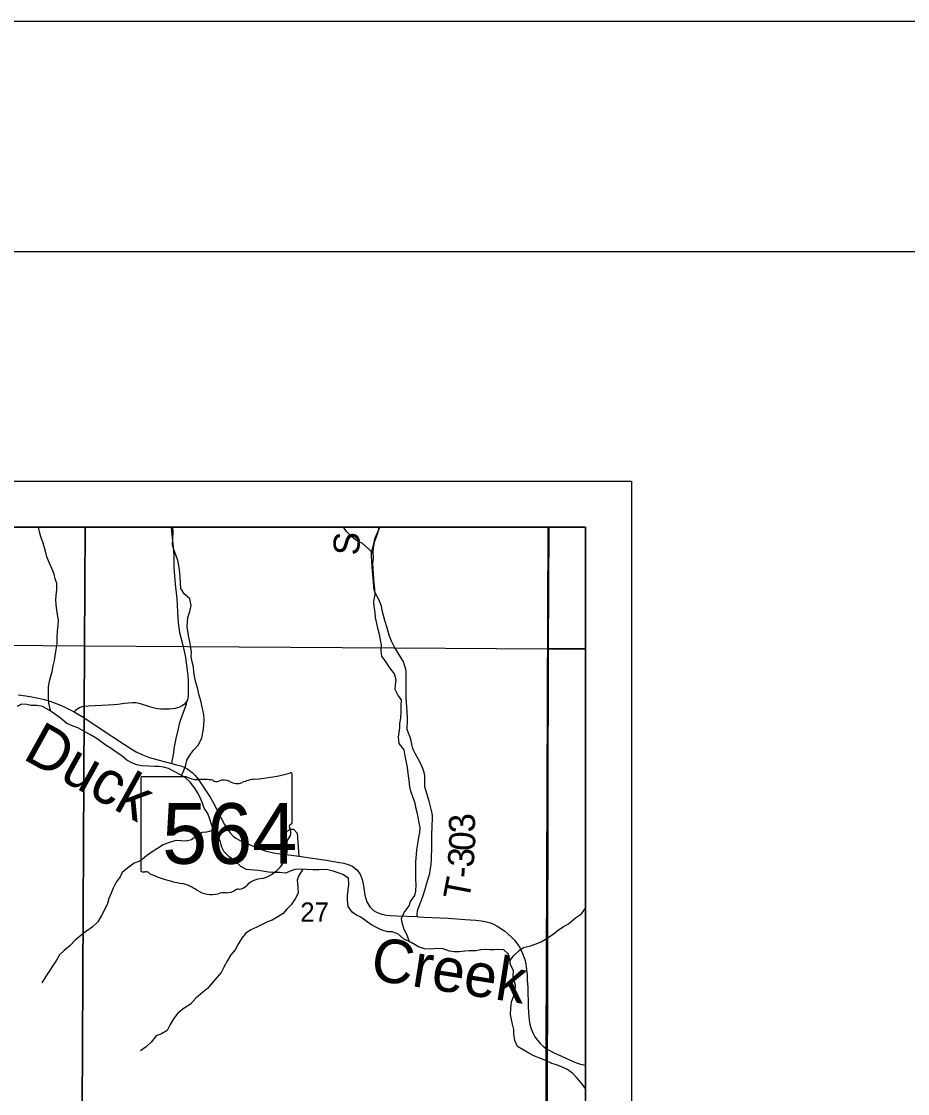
# Model space of a CAD drawing. Extents: x 0 to 34, y 0 to 22.
# Drawn here: x 7.673 to 9.601, y 19.668 to 22 of the extents above; entities that cross this region are included whole.
import ezdxf

# ---------------------------------------------------------------- set-up
doc = ezdxf.new("R2010")
doc.units = 0
for name, color, linetype in [('Default', 7, 'Continuous'), ('GM_X_Minor_River', 7, 'Continuous'), ('GM_X_Minor_River_Text', 7, 'Continuous'), ('GM_X_Rail_Line', 7, 'Continuous'), ('GM_X_Section', 7, 'Continuous'), ('GM_X_Section_Text', 7, 'Continuous'), ('GM_X_State_Location', 7, 'Continuous'), ('GM_X_State_Route', 7, 'Continuous'), ('GM_X_State_Shield', 7, 'Continuous'), ('GM_X_Township_Road', 7, 'Continuous'), ('GM_X_Township_Road_Text', 7, 'Continuous'), ('SH_Border', 7, 'Continuous'), ('SH_Cut_Line', 7, 'Continuous'), ('SH_Data', 7, 'Continuous')]:
    doc.layers.add(name, color=color, linetype=linetype)

msp = doc.modelspace()

# ---------------------------------------------------------------- linework, layer by layer
at = {"layer": 'Default'}
for points in [[(7.8121, 20.9), (6.8087, 20.9), (6.806, 20.65), (7.8107, 20.6421)], [(8.8202, 20.9), (7.8121, 20.9), (7.8107, 20.6421), (8.8188, 20.6358)], [(8.9, 20.6353), (8.9, 20.9), (8.8202, 20.9), (8.8188, 20.6358)], [(8.9, 19.6293), (8.9, 20.6353), (8.8188, 20.6358), (8.8166, 19.6292)]]:
    msp.add_lwpolyline(points, close=True, dxfattribs=at)
at = {"layer": 'GM_X_Minor_River'}
for points in [[(7.7374, 20.4995), (7.733, 20.5171), (7.7326, 20.5307), (7.7325, 20.5527), (7.7343, 20.5649), (7.7377, 20.5759), (7.7403, 20.5865), (7.7425, 20.5983), (7.7455, 20.6101), (7.747, 20.62), (7.7492, 20.634), (7.751, 20.6473), (7.751, 20.661), (7.7517, 20.6739), (7.7532, 20.6876), (7.7542, 20.697), (7.7504, 20.7198), (7.7488, 20.7323), (7.7484, 20.7418), (7.7487, 20.7513), (7.7502, 20.7638), (7.7501, 20.7775), (7.747, 20.7881), (7.7443, 20.7983), (7.7405, 20.8089), (7.7336, 20.823), (7.729, 20.8355), (7.7255, 20.8483), (7.7228, 20.8578), (7.7201, 20.8677), (7.7158, 20.879), (7.7124, 20.8897), (7.7104, 20.8999), (7.7104, 20.9)], [(8.0213, 20.3604), (8.0265, 20.3707), (8.031, 20.3836), (8.0328, 20.3931), (8.0392, 20.4026), (8.0471, 20.4144), (8.0585, 20.427), (8.066, 20.4419), (8.0686, 20.457), (8.0701, 20.4681), (8.0712, 20.4817), (8.0703, 20.492), (8.0657, 20.5124), (8.0634, 20.5223), (8.0595, 20.5371), (8.0572, 20.5481), (8.0529, 20.5625), (8.0499, 20.5758), (8.0487, 20.5856), (8.0475, 20.5966), (8.0448, 20.6076), (8.0428, 20.6179), (8.0432, 20.6281), (8.0416, 20.6387), (8.0396, 20.6516), (8.0373, 20.6611), (8.035, 20.6736), (8.0338, 20.6835), (8.0345, 20.6945), (8.0356, 20.704), (8.0394, 20.7165), (8.0423, 20.7298), (8.0396, 20.7442), (8.0282, 20.7548), (8.0201, 20.7669), (8.0193, 20.7775), (8.0185, 20.7927), (8.0169, 20.8075), (8.0154, 20.817), (8.0134, 20.8276), (8.0103, 20.8378), (8.0046, 20.8515), (8.0023, 20.8617), (8.0026, 20.875), (8.0033, 20.889), (8.0029, 20.9)], [(8.4388, 20.8421), (8.4276, 20.8537), (8.415, 20.8643), (8.4002, 20.8726), (8.3903, 20.8805), (8.3807, 20.8911), (8.3736, 20.9)], [(8.5173, 19.9986), (8.5118, 20.0142), (8.5057, 20.0255), (8.5011, 20.0399), (8.5003, 20.0494), (8.5059, 20.0623), (8.5165, 20.0764), (8.5199, 20.0863), (8.5293, 20.0989), (8.5315, 20.1088), (8.5319, 20.1228), (8.5311, 20.1334), (8.531, 20.1558), (8.5313, 20.1725), (8.5323, 20.1881), (8.5334, 20.1987), (8.5356, 20.2116), (8.5379, 20.2253), (8.5401, 20.2359), (8.5404, 20.2469), (8.5385, 20.2572), (8.5362, 20.2693), (8.5338, 20.2796), (8.5315, 20.2902), (8.5299, 20.3), (8.5253, 20.3118), (8.52, 20.3258), (8.5184, 20.3357), (8.5164, 20.3489), (8.5152, 20.3592), (8.514, 20.3717), (8.5125, 20.3816), (8.5098, 20.3922), (8.5078, 20.4028), (8.5059, 20.4157), (8.4952, 20.4297), (8.4936, 20.4433), (8.4951, 20.4536), (8.4962, 20.4635), (8.4965, 20.473), (8.4984, 20.4847), (8.4991, 20.4992), (8.4994, 20.5124), (8.5001, 20.5246), (8.4928, 20.5344), (8.4859, 20.5469), (8.487, 20.5576), (8.4885, 20.5671), (8.4846, 20.5811), (8.4747, 20.5939), (8.4667, 20.6068), (8.4575, 20.6197), (8.4559, 20.6311), (8.4563, 20.6443), (8.4543, 20.6546), (8.4528, 20.6641), (8.4493, 20.6773), (8.4462, 20.691), (8.4438, 20.7039), (8.4427, 20.7156), (8.4403, 20.7278), (8.4399, 20.7384), (8.4425, 20.754), (8.442, 20.7669), (8.4405, 20.7779), (8.4401, 20.7874), (8.4393, 20.7991), (8.4381, 20.8094), (8.438, 20.8219), (8.4391, 20.8325), (8.4387, 20.845), (8.4394, 20.8549), (8.442, 20.8694), (8.4454, 20.8792), (8.4491, 20.8891), (8.4516, 20.9)], [(8.3823, 20.0982), (8.3838, 20.1112), (8.3857, 20.1241), (8.3848, 20.137), (8.3723, 20.1449), (8.3624, 20.1482), (8.3517, 20.152), (8.3399, 20.1546), (8.3301, 20.1557), (8.3206, 20.1553), (8.3077, 20.1552), (8.2936, 20.1555), (8.2811, 20.1566), (8.2682, 20.1558), (8.2579, 20.1524), (8.2481, 20.1478), (8.2344, 20.1488), (8.2203, 20.1495), (8.2105, 20.1502), (8.1979, 20.1521), (8.1884, 20.1536), (8.1626, 20.1557), (8.1504, 20.1621), (8.1382, 20.1735), (8.1253, 20.1833), (8.1142, 20.1939), (8.1092, 20.2045), (8.1054, 20.2173), (8.1023, 20.2268), (8.0935, 20.2397), (8.0881, 20.2495), (8.0831, 20.2651), (8.0785, 20.2776), (8.0712, 20.2893), (8.067, 20.2999), (8.062, 20.3124), (8.0563, 20.323), (8.0505, 20.3329), (8.0406, 20.3457), (8.0292, 20.3559), (8.0178, 20.3623), (8.0067, 20.3683), (7.993, 20.3751), (7.9827, 20.3785), (7.9729, 20.3796), (7.9634, 20.3799), (7.9505, 20.3806), (7.9356, 20.3813), (7.9246, 20.3835), (7.9147, 20.3869), (7.9026, 20.3933), (7.8919, 20.4028), (7.8793, 20.4107), (7.8683, 20.4186), (7.858, 20.4254), (7.8458, 20.4344), (7.8363, 20.4416), (7.8222, 20.4495), (7.8089, 20.4563), (7.7959, 20.4638), (7.786, 20.4676), (7.7719, 20.4732), (7.7586, 20.4849), (7.7457, 20.4943), (7.7335, 20.5019), (7.7194, 20.5102), (7.7076, 20.5124), (7.6947, 20.5127), (7.6852, 20.5142), (7.6738, 20.5153), (7.6639, 20.5103)], [(8.0928, 20.241), (8.076, 20.237), (8.0665, 20.2362), (8.0559, 20.2293), (8.0434, 20.2201), (8.0317, 20.217), (8.0211, 20.2177), (8.01, 20.2188), (7.9971, 20.215), (7.9816, 20.2092), (7.9695, 20.2012), (7.9596, 20.1955), (7.9456, 20.1852), (7.9324, 20.1745), (7.9184, 20.1695), (7.9044, 20.1588), (7.8922, 20.1492), (7.8881, 20.1397), (7.8798, 20.1279), (7.8726, 20.1154), (7.8685, 20.104), (7.8633, 20.0926), (7.8603, 20.0816), (7.8554, 20.0709), (7.8478, 20.0553), (7.8399, 20.042), (7.8271, 20.0302), (7.815, 20.0218), (7.8028, 20.0122), (7.79, 20.0019), (7.7786, 19.9898), (7.7665, 19.9798), (7.7563, 19.9703), (7.7495, 19.9585), (7.7412, 19.9456), (7.7348, 19.9353), (7.7258, 19.922), (7.7179, 19.909)], [(8.2852, 20.1563), (8.277, 20.1429), (8.2732, 20.1327), (8.2748, 20.1171), (8.2752, 20.1042), (8.2685, 20.0917), (8.2598, 20.0791), (8.2507, 20.0696), (8.2424, 20.0601), (8.2307, 20.0524), (8.2185, 20.0455), (8.2087, 20.0417), (8.1969, 20.0363), (8.1852, 20.0302), (8.1727, 20.0245), (8.1606, 20.0164), (8.1526, 20.0065), (8.1458, 19.9944), (8.1383, 19.9811), (8.1289, 19.97), (8.1217, 19.9575), (8.1138, 19.943), (8.1078, 19.932), (8.0942, 19.916), (8.0859, 19.9065), (8.0779, 19.8969), (8.0669, 19.8885), (8.0537, 19.8763), (8.0412, 19.8626), (8.0276, 19.8538), (8.0136, 19.8432), (8.0042, 19.8306), (7.997, 19.8184), (7.9906, 19.8059), (7.9777, 19.7982), (7.9663, 19.794), (7.9554, 19.7803), (7.9448, 19.77), (7.9323, 19.7612)], [(8.9, 19.6793), (8.8907, 19.6917), (8.8823, 19.7016), (8.8717, 19.7129), (8.8595, 19.7212), (8.8465, 19.7272), (8.837, 19.731), (8.8271, 19.734), (8.8119, 19.7407), (8.7986, 19.7464), (8.7879, 19.7501), (8.7769, 19.7561), (8.7647, 19.7633), (8.7522, 19.7705), (8.7468, 19.7837), (8.7444, 19.7981), (8.744, 19.8076), (8.7417, 19.8194), (8.7394, 19.8296), (8.7374, 19.8406), (8.7381, 19.8531), (8.7396, 19.8679), (8.7441, 19.8812), (8.7474, 19.8922), (8.7482, 19.904), (8.7454, 19.9142), (8.7431, 19.9237), (8.7435, 19.9355), (8.7373, 19.9491), (8.7358, 19.9594), (8.7327, 19.9715), (8.7224, 19.9809), (8.7114, 19.9816), (8.7019, 19.9808), (8.6916, 19.9812), (8.6817, 19.9815), (8.6722, 19.9807), (8.6616, 19.9791), (8.6472, 19.9787), (8.6377, 19.9783), (8.6263, 19.9767), (8.6145, 19.9763), (8.6047, 19.9781), (8.5906, 19.983), (8.5765, 19.9837), (8.564, 19.9825), (8.5499, 19.9828), (8.537, 19.9877), (8.5222, 19.9964), (8.5043, 20.0047), (8.4917, 20.016), (8.4799, 20.0201), (8.4704, 20.0204), (8.4575, 20.0238), (8.4457, 20.0294), (8.4331, 20.0358), (8.4228, 20.0438), (8.4114, 20.0517), (8.4019, 20.0566), (8.3924, 20.063), (8.384, 20.0751), (8.3824, 20.0888), (8.3823, 20.0982)], [(8.736, 19.9576), (8.7426, 19.9674), (8.7558, 19.9792), (8.7656, 19.9857), (8.7808, 19.9895), (8.791, 19.993), (8.8039, 19.9987), (8.8153, 20.0056), (8.8301, 20.0152), (8.8418, 20.0247), (8.8516, 20.0308), (8.863, 20.0373), (8.8785, 20.0507), (8.8914, 20.0591), (8.9, 20.0714)]]:
    msp.add_lwpolyline(points, dxfattribs=at)
at = {"layer": 'GM_X_Rail_Line'}
for points in [[(5.4171, 18.6266), (7.3845, 18.6186), (7.3876, 18.6186), (7.7217, 18.6188), (7.7247, 18.6188), (7.7665, 18.6188), (7.7949, 18.6196), (7.7955, 18.662), (7.7955, 18.6643), (7.8036, 19.6113), (7.8037, 19.6169), (7.8038, 19.6317), (8.8143, 19.6303), (8.8149, 19.7665), (8.8193, 20.9), (4.5874, 20.9)], [(8.9, 14.624), (8.9, 20.9), (8.8193, 20.9), (8.8149, 19.7665), (8.8143, 19.6303), (7.8038, 19.6317), (7.8037, 19.6169), (7.8036, 19.6113), (7.7955, 18.6643), (7.7955, 18.662), (7.7949, 18.6196), (7.7665, 18.6188), (7.7247, 18.6188), (7.7217, 18.6188), (7.3876, 18.6186), (7.3845, 18.6186), (5.4171, 18.6266)]]:
    msp.add_lwpolyline(points, dxfattribs=at)
at = {"layer": 'GM_X_Section'}
for points in [[(6.806, 20.65), (7.8107, 20.6421), (7.8055, 19.6329), (6.8002, 19.6351)], [(7.8107, 20.6421), (8.8188, 20.6358), (8.8166, 19.6292), (7.8055, 19.6329)]]:
    msp.add_lwpolyline(points, close=True, dxfattribs=at)
at = {"layer": 'GM_X_State_Route'}
for points in [[(7.666, 20.5356), (7.6827, 20.5331), (7.6963, 20.5311), (7.7107, 20.5284), (7.7235, 20.5252), (7.7396, 20.5205), (7.7622, 20.5118), (7.7882, 20.4983), (7.8088, 20.4859), (7.8449, 20.4623), (7.8978, 20.4272), (7.9123, 20.4179), (7.9232, 20.4115), (7.9356, 20.4055), (7.9498, 20.4), (7.962, 20.3964), (7.9806, 20.391), (8.0006, 20.3862), (8.008, 20.3841), (8.0134, 20.3827), (8.0199, 20.3809), (8.027, 20.3782), (8.0334, 20.3751), (8.0392, 20.3713), (8.0447, 20.3666), (8.0503, 20.361), (8.0554, 20.3548), (8.0651, 20.3413), (8.0695, 20.3346), (8.0766, 20.3241), (8.0836, 20.313), (8.0901, 20.3016), (8.0952, 20.2921), (8.0992, 20.2842), (8.1069, 20.2687), (8.115, 20.2533), (8.1207, 20.244), (8.1274, 20.2355), (8.134, 20.2281), (8.1396, 20.2238), (8.1449, 20.2206), (8.1515, 20.2173), (8.1646, 20.2119)], [(8.1646, 20.2119), (8.1805, 20.2053), (8.1936, 20.1999), (8.2036, 20.1965), (8.2219, 20.1921), (8.2408, 20.1892), (8.261, 20.1865), (8.2768, 20.1846), (8.3359, 20.176), (8.3654, 20.1711), (8.3747, 20.1693), (8.3843, 20.1664), (8.3933, 20.1627), (8.4032, 20.1553), (8.4102, 20.1455), (8.4146, 20.1341), (8.4167, 20.1248), (8.4184, 20.1151), (8.4206, 20.1001), (8.4247, 20.0857), (8.4314, 20.0743), (8.4394, 20.0667), (8.4469, 20.0618), (8.4572, 20.0584), (8.4677, 20.0562), (8.4762, 20.0554), (8.4902, 20.0549), (8.5339, 20.0532), (8.5377, 20.0529), (8.5491, 20.0523), (8.5842, 20.0505)], [(8.5842, 20.0505), (8.6013, 20.0496), (8.6382, 20.0473), (8.6617, 20.0458), (8.674, 20.0439), (8.6849, 20.042), (8.6934, 20.0394), (8.7016, 20.036), (8.7084, 20.0323), (8.7139, 20.029), (8.7241, 20.022), (8.7322, 20.0153), (8.7395, 20.0086), (8.7462, 20.0011), (8.7524, 19.9933), (8.7573, 19.9857), (8.7631, 19.9732), (8.768, 19.9597), (8.7706, 19.9496), (8.7712, 19.944), (8.7731, 19.926), (8.7735, 19.915), (8.7744, 19.8991), (8.7755, 19.8567), (8.7761, 19.8444), (8.7778, 19.8283), (8.7793, 19.8196), (8.782, 19.8089), (8.7861, 19.7991), (8.7899, 19.7921), (8.7947, 19.7849), (8.8022, 19.7766), (8.8089, 19.7711), (8.8151, 19.766), (8.832, 19.7573), (8.8482, 19.7495), (8.8785, 19.736), (8.8891, 19.7325), (8.9, 19.7299)]]:
    msp.add_lwpolyline(points, dxfattribs=at)
at = {"layer": 'GM_X_State_Shield'}
for p, q in [((8.0325, 20.3575), (7.936, 20.3575)), ((8.2624, 20.2578), (8.2624, 20.3625)), ((7.9328, 20.3541), (7.9328, 20.154)), ((8.2623, 20.2578), (8.2624, 20.2578))]:
    msp.add_line(p, q, dxfattribs=at)
for centre, major_axis, start_param, end_param in [((7.9366, 20.3545), (0.00382, 0), 1.712693, 3.28349), ((8.0555, 20.3807), (0.037, 0), 4.042523, 4.731795), ((8.145, 20.6303), (0.3495, 0), 4.814394, 5.042369), ((8.2587, 20.3629), (0.00367, 0), 6.141152, 7.989035), ((8.0678, 20.2452), (0.133, 0), 1.404758, 1.657858), ((8.098, 20.3555), (0.0107, 0), 3.836095, 5.185415), ((8.1137, 20.3324), (0.0222, 0), 0.950623, 2.079405), ((8.1423, 20.3641), (0.0267, 0), 4.081561, 5.145723), ((8.1895, 20.2964), (0.0703, 0), 1.699011, 2.107814), ((8.2615, 20.2501), (0.00568, 0), 1.883978, 3.671073), ((8.2254, 20.2369), (0.0341, 0), 5.934695, 6.695948), ((8.2584, 20.2574), (0.00393, 0), 5.05454, 6.418171), ((8.2755, 20.214), (0.0248, 0), 2.387724, 3.262537), ((8.1645, 20.2007), (0.0874, 0), 5.101752, 6.440018), ((7.9366, 20.1535), (0.00385, 0), 3.00124, 4.508301), ((7.9372, 20.174), (0.0294, 0), 4.665946, 4.897461), ((7.9432, 20.1424), (0.0106, 0), 0.519207, 1.627899), ((8.077, 20.3222), (0.2524, 0), 4.195997, 4.488961), ((8.0018, 20.064), (0.079, 0), 0.823519, 1.323587), ((8.2014, 20.0978), (0.0479, 0), 1.647645, 2.488434), ((8.0872, 20.1414), (0.0501, 0), 4.026481, 4.996735), ((8.1161, 20.0722), (0.0412, 0), 1.495662, 1.94098), ((8.1198, 20.1264), (0.0267, 0), 4.691044, 5.507374), ((8.1439, 20.107), (0.00752, 0), 1.147584, 2.315152), ((8.1407, 20.1346), (0.0282, 0), 4.937069, 5.64225)]:
    msp.add_ellipse(centre, major_axis=major_axis, ratio=0.8, start_param=start_param, end_param=end_param, dxfattribs=at)
at = {"layer": 'GM_X_Township_Road'}
for points in [[(7.9988, 20.9), (7.9998, 20.8918), (8.0033, 20.8569), (8.0046, 20.8375), (8.0051, 20.8121), (8.0081, 20.7763), (8.0112, 20.7444), (8.012, 20.7314), (8.0129, 20.7154), (8.0144, 20.6926), (8.0156, 20.6812), (8.0175, 20.6714), (8.0203, 20.6604), (8.0253, 20.6408), (8.03, 20.6169), (8.0335, 20.5945), (8.035, 20.5779), (8.036, 20.566), (8.0363, 20.5551), (8.0364, 20.5428), (8.0358, 20.5348), (8.0351, 20.5285), (8.0345, 20.5249), (8.0309, 20.5187), (8.0279, 20.5153), (8.0233, 20.5118), (8.019, 20.5094), (8.0152, 20.5079), (8.0068, 20.506), (7.9953, 20.5045), (7.9851, 20.5044), (7.9764, 20.5045), (7.9694, 20.5053), (7.9601, 20.507), (7.9504, 20.5099), (7.9323, 20.5163), (7.9225, 20.5181), (7.9149, 20.5183), (7.9054, 20.5177), (7.8977, 20.5165), (7.8828, 20.5146), (7.8737, 20.5136), (7.8621, 20.5128), (7.8337, 20.5115), (7.8189, 20.5112), (7.8096, 20.5104), (7.8046, 20.5094), (7.8, 20.5075), (7.7939, 20.5039), (7.7908, 20.5012), (7.7882, 20.4983)], [(8.5667, 20.2783), (8.5646, 20.2872), (8.5602, 20.3041), (8.5528, 20.3279), (8.5511, 20.3357), (8.551, 20.3545), (8.5506, 20.3599), (8.5494, 20.3666), (8.5461, 20.3756), (8.5396, 20.3896), (8.5296, 20.408), (8.5267, 20.4134), (8.5248, 20.4188), (8.5233, 20.4245), (8.5208, 20.4355), (8.5185, 20.4435), (8.5149, 20.4525), (8.5126, 20.4603), (8.5124, 20.4666), (8.5132, 20.4757), (8.5131, 20.4872), (8.5116, 20.5089), (8.5105, 20.5295), (8.5099, 20.545), (8.51, 20.5632), (8.5105, 20.5714), (8.5104, 20.5813), (8.5103, 20.586), (8.5094, 20.5916), (8.5068, 20.6004), (8.504, 20.607), (8.4998, 20.6142), (8.494, 20.6237), (8.4838, 20.641), (8.478, 20.6519), (8.4735, 20.6656), (8.4686, 20.6814), (8.4634, 20.6974), (8.458, 20.7191), (8.4562, 20.7286), (8.4539, 20.7359), (8.451, 20.7425), (8.447, 20.7497), (8.4428, 20.7575), (8.4408, 20.7636), (8.4398, 20.7704), (8.4391, 20.7807), (8.4381, 20.7892), (8.4363, 20.8129), (8.4356, 20.826), (8.4349, 20.8374), (8.4349, 20.844), (8.4356, 20.849), (8.4374, 20.8555), (8.4429, 20.8767), (8.4511, 20.8966), (8.4532, 20.9)], [(8.0006, 20.3862), (8.0042, 20.4059), (8.0064, 20.4222), (8.0101, 20.4404), (8.014, 20.4588), (8.0182, 20.4751), (8.0237, 20.4921), (8.0297, 20.5071), (8.0323, 20.5158), (8.0345, 20.5249)], [(8.5339, 20.0532), (8.5341, 20.0586), (8.5351, 20.0657), (8.5367, 20.0724), (8.5403, 20.0817), (8.5471, 20.0994), (8.5513, 20.1129), (8.5551, 20.1261), (8.5596, 20.1405), (8.5613, 20.1468), (8.5627, 20.154), (8.5638, 20.1614), (8.5644, 20.1677), (8.5652, 20.1768), (8.5656, 20.1864), (8.5662, 20.1984), (8.5661, 20.2099), (8.5663, 20.2294), (8.5668, 20.2503), (8.5671, 20.2666), (8.5673, 20.2726), (8.5669, 20.2774), (8.5667, 20.2783)], [(8.2408, 20.1892), (8.2492, 20.2364), (8.2568, 20.2436), (8.2652, 20.2435), (8.2731, 20.2348), (8.2768, 20.1846)]]:
    msp.add_lwpolyline(points, dxfattribs=at)
at = {"layer": 'SH_Border'}
msp.add_lwpolyline([(1.5, 21.5), (33.5, 21.5), (33.5, 0.5), (1.5, 0.5)], close=True, dxfattribs=at)
at = {"layer": 'SH_Cut_Line'}
msp.add_lwpolyline([(0, 0), (34, 0), (34, 22), (0, 22)], close=True, dxfattribs=at)
msp.add_lwpolyline([(8.9, 14.624), (8.9, 20.9), (2.1, 20.9), (2.1, 14.1)], dxfattribs=at)
at = {"layer": 'SH_Data'}
for p, q in [((2, 21), (9, 21)), ((9, 21), (9, 14)), ((2.1, 20.9), (8.9, 20.9)), ((8.9, 20.9), (8.9, 14.1))]:
    msp.add_line(p, q, dxfattribs=at)

# ---------------------------------------------------------------- texts
at = {"layer": 'GM_X_Minor_River_Text'}
for s, height, rotation, p in [('Duck', 0.09471, 330.9944, (7.6736, 20.3975)), ('Creek', 0.0947, 350.9996, (8.4296, 19.9166))]:
    msp.add_text(s, height=height, rotation=rotation, dxfattribs=at).set_placement(p)
at = {"layer": 'GM_X_Section_Text'}
msp.add_text('27', height=0.04186, rotation=0, dxfattribs=at).set_placement((8.2799, 20.0421))
at = {"layer": 'GM_X_State_Location'}
for s in ['s', 'r']:
    msp.add_text(s, height=0.000189, dxfattribs=at).set_placement((8.0939, 20.2407))
msp.add_text('564', height=0.000189, rotation=0, dxfattribs=at).set_placement((8.027, 20.2269))
at = {"layer": 'GM_X_State_Shield'}
msp.add_text('564', height=0.13184, dxfattribs=at).set_placement((7.9793, 20.1681))
at = {"layer": 'GM_X_Township_Road_Text'}
for s, rotation, p in [('S', 87.4095, (8.408, 20.8379)), ('3', 93.4033, (8.6611, 20.237)), ('0', 86.6774, (8.6591, 20.1947)), ('3', 85.9062, (8.6565, 20.159)), ('-', 86.2056, (8.655, 20.1358)), ('T', 79.2053, (8.6461, 20.0865))]:
    msp.add_text(s, height=0.0568, rotation=rotation, dxfattribs=at).set_placement(p)

doc.saveas('drawing.dxf')
